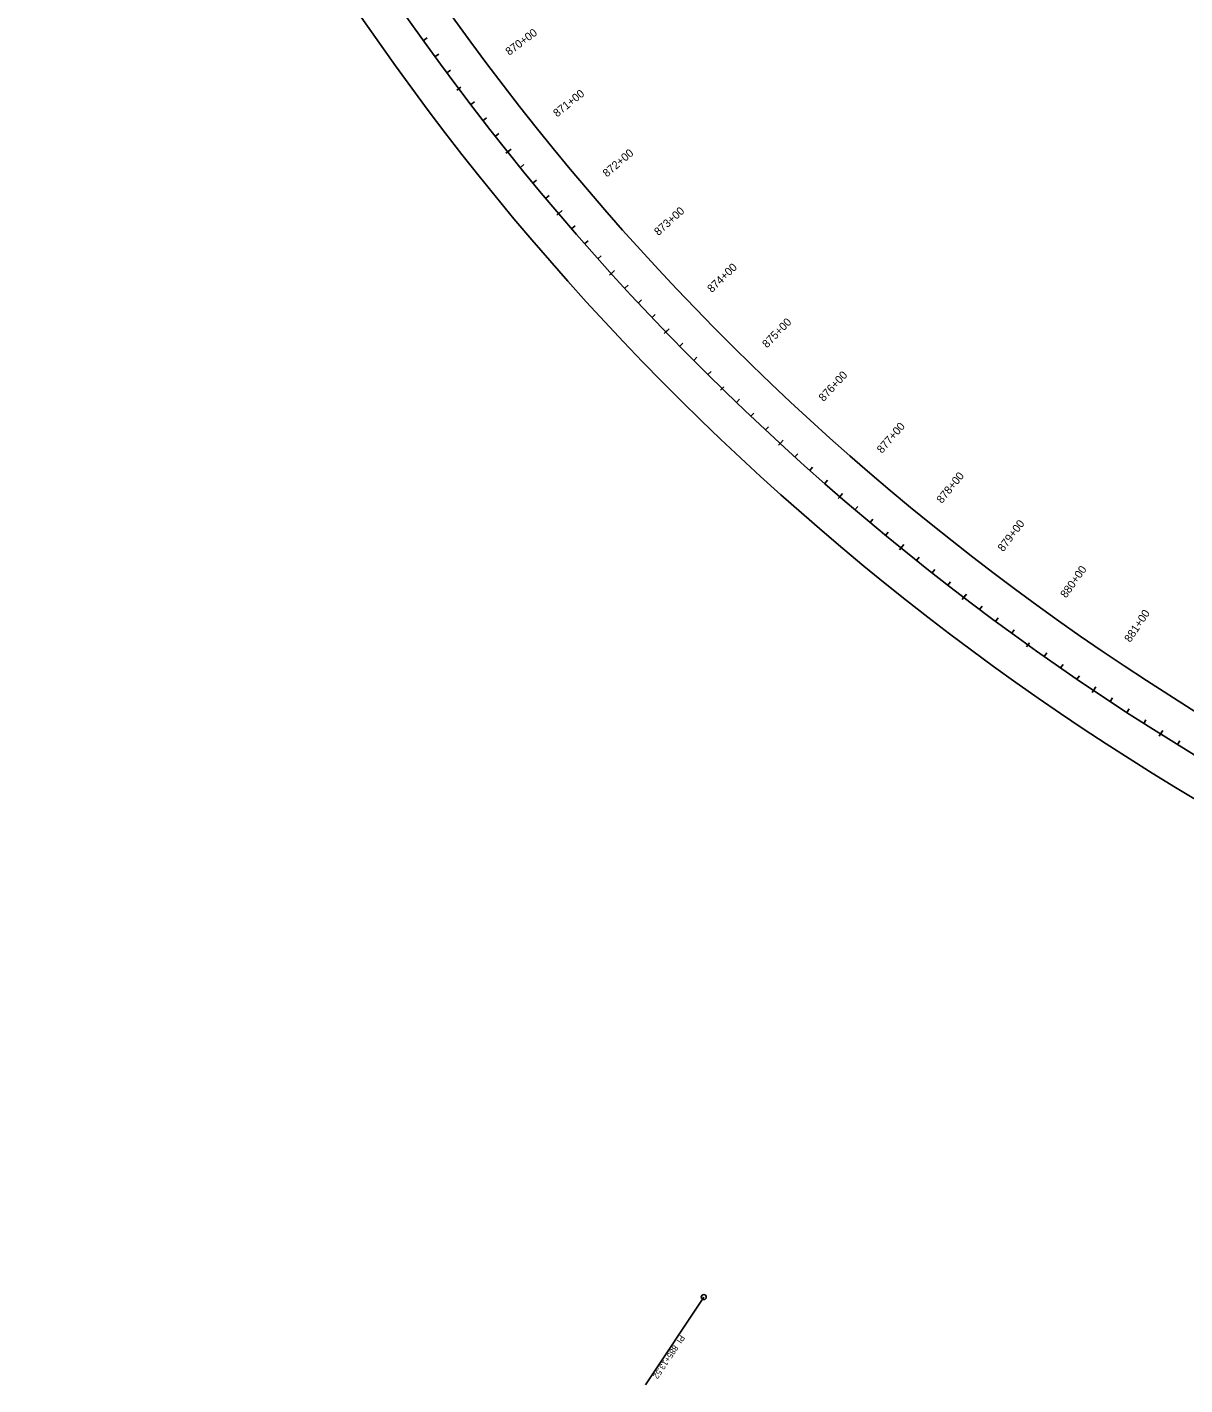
# Model space of a CAD drawing. Extents: x 14448949 to 14455476, y 8570587 to 8573998.
# Drawn here: x 14449299 to 14450748, y 8570587 to 8572286 of the extents above; entities that cross this region are included whole.
import ezdxf

# ---------------------------------------------------------------- set-up
doc = ezdxf.new("R2010")
doc.units = 0
for name, color, linetype in [('Alignment', 7, 'Continuous'), ('TextAlignment', 7, 'Continuous'), ('TextAlignmentLrg', 7, 'Continuous'), ('TextAlignmentSml', 7, 'Continuous'), ('TextNonPlot', 7, 'Continuous')]:
    doc.layers.add(name, color=color, linetype=linetype)

msp = doc.modelspace()

# ---------------------------------------------------------------- linework, layer by layer
at = {"layer": 'Alignment'}
msp.add_arc((14452465.5, 8574183.5), 3285.7, 198.0445, 274.688, dxfattribs=at)
msp.add_arc((14452465.5, 8574183.5), 3285.7, 198.0445, 274.688, dxfattribs=at)
at = {"layer": 'TextAlignment'}
for p in [(14450145.8, 8570696.6), (14450072.7, 8570586.7)]:
    msp.add_line(p, (14450072.7, 8570586.7), dxfattribs=at)
msp.add_circle((14450145.8, 8570696.6), 3.12, dxfattribs=at)
at = {"layer": 'TextAlignmentLrg'}
for p, q in [((14449841.6, 8572210.9), (14449836.8, 8572207.2)), ((14449900.5, 8572130.1), (14449904.8, 8572133.5)), ((14449964.2, 8572053), (14449968.3, 8572056.5)), ((14450030.2, 8571977.8), (14450034.2, 8571981.5)), ((14450098.4, 8571904.8), (14450102.3, 8571908.5)), ((14450171, 8571836), (14450166.7, 8571831.6)), ((14450241.4, 8571765), (14450245.1, 8571769)), ((14450316.1, 8571698.4), (14450319.6, 8571702.6)), ((14450392.7, 8571634.2), (14450396.1, 8571638.4)), ((14450471.2, 8571572.3), (14450474.5, 8571576.6)), ((14450553.4, 8571515.3), (14450549.8, 8571510.3)), ((14450633.8, 8571455.8), (14450636.8, 8571460.3)), ((14450717.6, 8571401.3), (14450720.5, 8571405.9))]:
    msp.add_line(p, q, dxfattribs=at)
at = {"layer": 'TextAlignmentSml'}
for p, q in [((14449794.8, 8572269.5), (14449799.3, 8572272.7)), ((14449809.5, 8572249.3), (14449813.9, 8572252.5)), ((14449824.3, 8572229.1), (14449828.6, 8572232.4)), ((14449841.6, 8572210.9), (14449836.8, 8572207.2)), ((14449854.3, 8572189.2), (14449858.6, 8572192.5)), ((14449869.5, 8572169.3), (14449873.9, 8572172.7)), ((14449885, 8572149.7), (14449889.2, 8572153)), ((14449902.9, 8572132), (14449898.1, 8572128.2)), ((14449916.2, 8572110.6), (14449920.4, 8572114.1)), ((14449932, 8572091.3), (14449936.3, 8572094.8)), ((14449948, 8572072.1), (14449952.2, 8572075.6)), ((14449966.5, 8572055), (14449961.8, 8572051)), ((14449980.5, 8572034), (14449984.6, 8572037.6)), ((14449996.9, 8572015.2), (14450001, 8572018.8)), ((14450013.5, 8571996.4), (14450017.5, 8572000.1)), ((14450032.4, 8571979.9), (14450027.9, 8571975.8)), ((14450047, 8571959.4), (14450051, 8571963.1)), ((14450064, 8571941), (14450068, 8571944.8)), ((14450081.1, 8571922.8), (14450085.1, 8571926.6)), ((14450100.6, 8571906.9), (14450096.2, 8571902.6)), ((14450115.8, 8571886.8), (14450119.7, 8571890.6)), ((14450133.4, 8571869), (14450137.2, 8571872.9)), ((14450151, 8571851.3), (14450154.9, 8571855.2)), ((14450171, 8571836), (14450166.7, 8571831.6)), ((14450186.8, 8571816.4), (14450190.6, 8571820.3)), ((14450204.9, 8571799.1), (14450208.6, 8571803.1)), ((14450223.1, 8571782), (14450226.8, 8571786)), ((14450243.5, 8571767.2), (14450239.4, 8571762.7)), ((14450259.9, 8571748.1), (14450263.6, 8571752.2)), ((14450278.5, 8571731.4), (14450282.1, 8571735.5)), ((14450297.2, 8571714.9), (14450300.8, 8571719)), ((14450318.1, 8571700.7), (14450314, 8571696.1)), ((14450335, 8571682.1), (14450338.6, 8571686.3)), ((14450354.1, 8571666), (14450357.6, 8571670.2)), ((14450373.3, 8571650), (14450376.8, 8571654.2)), ((14450394.6, 8571636.5), (14450390.7, 8571631.8)), ((14450412.1, 8571618.5), (14450415.5, 8571622.7)), ((14450431.7, 8571602.9), (14450435.1, 8571607.2)), ((14450451.4, 8571587.5), (14450454.7, 8571591.8)), ((14450473.1, 8571574.7), (14450469.4, 8571569.8)), ((14450491.1, 8571557.2), (14450494.4, 8571561.5)), ((14450511.2, 8571542.2), (14450514.4, 8571546.6)), ((14450531.3, 8571527.4), (14450534.5, 8571531.9)), ((14450553.4, 8571515.3), (14450549.8, 8571510.3)), ((14450572, 8571498.3), (14450575.1, 8571502.8)), ((14450592.5, 8571484), (14450595.6, 8571488.5)), ((14450613, 8571469.8), (14450616.1, 8571474.3)), ((14450635.5, 8571458.3), (14450632, 8571453.3)), ((14450654.6, 8571441.9), (14450657.6, 8571446.5)), ((14450675.5, 8571428.2), (14450678.4, 8571432.8)), ((14450696.5, 8571414.7), (14450699.4, 8571419.3)), ((14450719.2, 8571403.9), (14450716, 8571398.7)), ((14450738.8, 8571388.1), (14450741.7, 8571392.8))]:
    msp.add_line(p, q, dxfattribs=at)
at = {"layer": 'TextNonPlot'}
for centre, radius, start, end in [((14452466.6, 8574184.2), 3240, 198.0445, 274.688), ((14452464.1, 8574181.3), 3330, 198.0899, 274.6933)]:
    msp.add_arc(centre, radius, start, end, dxfattribs=at)

# ---------------------------------------------------------------- texts
at = {"layer": 'TextAlignment'}
for s, p in [('885+13.52', (14450108.2, 8570637.2)), ('PI ', (14450116.5, 8570649.7))]:
    msp.add_text(s, height=7.5, rotation=236.3663, dxfattribs=at).set_placement(p)
at = {"layer": 'TextAlignmentLrg'}
for s, rotation, p in [('870+00', 36.9365, (14449902.2, 8572250.1)), ('875+00', 45.6555, (14450224.9, 8571883.9)), ('880+00', 54.3745, (14450599.4, 8571570.8))]:
    msp.add_text(s, height=10.02, rotation=rotation, dxfattribs=at).set_placement(p)
at = {"layer": 'TextAlignmentSml'}
for s, rotation, p in [('870+00', 36.9365, (14449902.2, 8572250.1)), ('871+00', 38.6803, (14449962.2, 8572173)), ('872+00', 40.4241, (14450024.5, 8572097.8)), ('873+00', 42.1679, (14450089.1, 8572024.5)), ('874+00', 43.9117, (14450155.9, 8571953.2)), ('875+00', 45.6555, (14450224.9, 8571883.9)), ('876+00', 47.3993, (14450295.9, 8571816.8)), ('877+00', 49.1431, (14450368.9, 8571751.9)), ('878+00', 50.8869, (14450443.9, 8571689.2)), ('879+00', 52.6307, (14450520.7, 8571628.8)), ('880+00', 54.3745, (14450599.4, 8571570.8)), ('881+00', 56.1183, (14450679.7, 8571515.3))]:
    msp.add_text(s, height=10.02, rotation=rotation, dxfattribs=at).set_placement(p)

doc.saveas('drawing.dxf')
